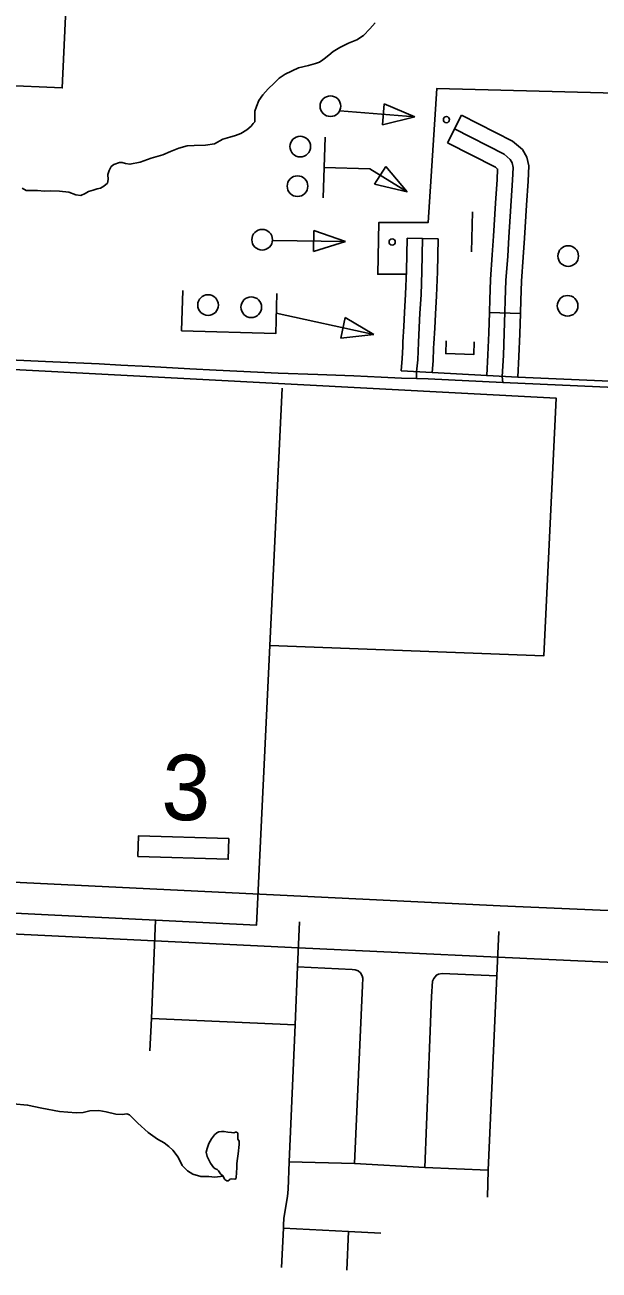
# Model space of a CAD drawing. Extents: x 653372 to 905732, y 627442 to 787275.
# Drawn here: x 684356 to 687136, y 777979 to 784006 of the extents above; entities that cross this region are included whole.
import ezdxf

# ---------------------------------------------------------------- set-up
doc = ezdxf.new("R2010")
doc.units = 0
for name, color, linetype in [('10', 7, 'Continuous'), ('33', 7, 'Continuous'), ('34', 7, 'Continuous'), ('35', 7, 'Continuous'), ('45', 7, 'Continuous'), ('5', 7, 'Continuous'), ('56', 7, 'Continuous'), ('6', 7, 'Continuous')]:
    doc.layers.add(name, color=color, linetype=linetype)

msp = doc.modelspace()

# ---------------------------------------------------------------- linework, layer by layer
at = {"layer": '10'}
for points in [[(684164.8, 779862.7), (684995.2, 779822.6), (685691.9, 779789.5), (686657, 779743.1), (687327.8, 779712.9), (687878.5, 779685.6)], [(687868.9, 779435.8), (687316, 779463.2), (686645.4, 779493.4), (685680, 779539.7), (684983.2, 779572.9), (684153, 779613)]]:
    msp.add_lwpolyline(points, dxfattribs=at)
at = {"layer": '33'}
for points in [[(684989, 779673.1), (684969.8, 779197.5), (684961.5, 779041)], [(685686, 779664.6), (685675.2, 779446.4), (685664, 779166), (685635.9, 778503), (685630.2, 778370.3), (685628.3, 778335.7), (685609.9, 778230.4), (685608.1, 778197.5), (685607.6, 778181.9), (685598.7, 777992.3)], [(686651.2, 779618.3), (686641.1, 779403.1), (686599.6, 778462.2), (686595.7, 778332)], [(685951.2, 778494.4), (685990.7, 779356.5), (685991.7, 779392), (685988.7, 779404), (685981.5, 779417.7), (685969.1, 779427.4), (685955.7, 779432.1), (685940.5, 779434.2), (685675.2, 779446.4)], [(686292, 778475.7), (686317.3, 779094.8), (686325.4, 779303.7), (686329.5, 779377.3), (686335.6, 779391.3), (686348.4, 779407), (686358, 779412.4), (686377, 779414.6), (686641.1, 779403.1)], [(684969.8, 779197.5), (685664, 779166)], [(686599.6, 778462.2), (686292, 778475.7), (685951.2, 778494.4), (685635.9, 778503)], [(685607.6, 778181.9), (685922.7, 778165.7), (686079.9, 778158.5)], [(685915, 777979.2), (685922.7, 778165.7)]]:
    msp.add_lwpolyline(points, dxfattribs=at)
at = {"layer": '34'}
for points in [[(687212.2, 782250.7), (686669.3, 782274.8), (686307.8, 782293.3), (686251.8, 782294.9), (686180.2, 782297.1), (686080.3, 782302), (685948.3, 782307.8), (685774.6, 782314.9), (685581.6, 782321.4), (685281.6, 782336), (685155.1, 782342.3), (684957.8, 782352.7), (684820.9, 782359.3), (684716, 782365.6), (684490.8, 782374.9), (684244, 782387.3), (683822.2, 782407.5), (683520.4, 782423.2), (683285.4, 782434), (682978.4, 782447.7)], [(686251.8, 782294.9), (686252.4, 782327.4)], [(686667, 782304.3), (686669.3, 782274.8)]]:
    msp.add_lwpolyline(points, dxfattribs=at)
at = {"layer": '35'}
for points in [[(686052, 784016), (686026.8, 783987.1), (685996.2, 783955.7), (685962.6, 783933.7), (685923.5, 783917.5), (685880.1, 783897.7), (685848.9, 783877.7), (685827.9, 783860.6), (685805.6, 783842.1), (685799.2, 783836.8), (685782.4, 783826.1), (685763.7, 783818.8), (685728.5, 783809.2), (685680.1, 783798.2), (685616.6, 783767.8), (685587.6, 783748.2), (685562.5, 783724.6), (685534.1, 783697.7), (685508.8, 783667.5), (685489.5, 783641.1), (685476.8, 783611.8), (685469.5, 783588.3), (685468.6, 783560.6), (685468.9, 783546.1), (685468.6, 783537.5), (685461.8, 783529.2), (685450.9, 783517), (685430.5, 783498.5), (685401.7, 783481.5), (685375.7, 783471.2), (685348.4, 783463.4), (685313.8, 783452.6)], [(685313.8, 783452.6), (685273.6, 783431), (685230.4, 783424), (685175.2, 783423.4), (685141.2, 783421.4), (685100.8, 783409.8), (685060.4, 783394.4), (685023.6, 783378.1), (684968, 783360.9), (684913.8, 783341.4), (684864.5, 783332.3), (684842.7, 783336), (684827.7, 783341), (684814.1, 783339.9), (684787.4, 783330.9), (684774.3, 783320.7), (684763.9, 783302.1), (684757.3, 783282.7), (684758.8, 783257.7), (684755.3, 783240.4), (684738.2, 783225.1), (684722.1, 783215.8), (684705.4, 783213.2), (684687.1, 783207), (684663.4, 783199.4), (684647.3, 783190.8), (684627.2, 783180.8), (684603.1, 783184.6), (684569.5, 783196.2), (684523.6, 783201.3), (684478.4, 783202.7), (684450.4, 783201.3), (684417.3, 783205.3), (684382.5, 783204.1), (684362.9, 783205.4), (684342.9, 783216.6)], [(685315.8, 778434.1), (685274.9, 778429), (685246.5, 778431.6), (685226.7, 778432.2), (685207.7, 778432.7), (685169.2, 778444.3), (685143.8, 778459.7), (685117, 778485.5), (685098.3, 778525.8), (685072.6, 778559.4), (685052.4, 778578.1), (685030.5, 778595.2), (684997.4, 778613.4), (684953.5, 778645.8), (684903.1, 778690.5), (684862, 778730.6), (684849.2, 778735.3), (684826.6, 778731.7), (684795.6, 778734.3), (684750.2, 778745.2), (684714.2, 778751.4), (684671, 778750.1), (684638.8, 778742.5), (684605.1, 778740), (684523.8, 778746.8), (684437.9, 778763.2), (684369.4, 778778.2), (684298.8, 778784.6)], [(685270.7, 778474.5), (685254.1, 778497.4), (685238.8, 778529.1), (685234.4, 778549.4), (685238.9, 778567.6), (685247.4, 778592.5), (685259.8, 778613.9), (685273.8, 778633.6), (685284.7, 778643.3), (685295.5, 778649.2), (685307.8, 778649.9), (685320.1, 778649.5)], [(685320.1, 778649.5), (685339, 778646.7), (685355.6, 778644.6), (685367.3, 778643.1), (685375.3, 778647.3), (685380.3, 778647.2), (685385.8, 778644.2), (685386.8, 778639.7), (685387.3, 778632.4), (685387.3, 778612.3), (685392.9, 778603.8), (685393.9, 778598.2), (685394.1, 778587), (685388.8, 778541.4), (685385.9, 778518.6), (685383, 778495.7), (685383, 778477.3), (685381, 778447.8), (685379.3, 778428.3), (685377.4, 778421.6), (685372.9, 778419.5), (685354.5, 778420.6), (685348.9, 778418.6), (685344.8, 778414.2), (685339.7, 778411.6), (685333.5, 778410.7), (685324.3, 778417.6), (685318.9, 778425.6), (685315.8, 778434.1), (685303.3, 778445.6), (685293.7, 778459.9), (685286.6, 778466.2), (685278.9, 778469.8), (685270.7, 778474.5)]]:
    msp.add_lwpolyline(points, dxfattribs=at)
at = {"layer": '45'}
for p, q in [((686402.1, 783435.9), (686470.3, 783569.5)), ((686206.8, 782974.1), (686356.8, 782970.8)), ((686605, 782613.9), (686754.9, 782609.4))]:
    msp.add_line(p, q, dxfattribs=at)
for points in [[(686470.3, 783569.5), (686717.4, 783443.4), (686765.1, 783403.5), (686785.8, 783365.7), (686795.4, 783323.7), (686792.1, 783250.7), (686784.6, 783134)], [(686436.2, 783502.7), (686675.7, 783380.5), (686706.1, 783355.1), (686715, 783338.8), (686720, 783316.9), (686717.2, 783254.8), (686699.5, 782979), (686693.9, 782887.6), (686684.7, 782770), (686681.9, 782673.9), (686680.1, 782615.5), (686677, 782513.7), (686672.8, 782405.4), (686667, 782304.3)], [(686402.1, 783435.9), (686634.1, 783317.5), (686644.6, 783308.7), (686642.3, 783258.8), (686634.9, 783143.6)], [(686634.9, 783143.6), (686624.6, 782983.6), (686619.1, 782892.9), (686609.8, 782774.1), (686606.9, 782676.2), (686605.1, 782617.8), (686605, 782613.9)], [(686784.6, 783134), (686774.4, 782974.3), (686768.7, 782882.4), (686759.6, 782766), (686756.8, 782671.7), (686755.1, 782613.3), (686754.9, 782609.4)], [(686206.8, 782974.1), (686203.3, 782815.3), (686199.4, 782703.1), (686193.6, 782614.6), (686190.3, 782546.4), (686186.1, 782471.9), (686185.2, 782447.8)], [(686281.8, 782972.4), (686278.3, 782813.1), (686274.3, 782699.3), (686268.4, 782610.4), (686265.2, 782542.5), (686261, 782468.4), (686257.9, 782386), (686252.4, 782327.4)], [(686356.8, 782970.8), (686353.3, 782811), (686349.2, 782695.6), (686343.3, 782606.1), (686340.1, 782538.6), (686336, 782464.9), (686335.1, 782442.1)], [(686605, 782613.9), (686602.1, 782516.3), (686597.9, 782409), (686592.1, 782308.6), (686741.9, 782301.1)], [(686754.9, 782609.4), (686752, 782511.2), (686747.8, 782401.8), (686741.9, 782301.1)], [(686185.2, 782447.8), (686183.1, 782391), (686177.5, 782331.6)], [(686335.1, 782442.1), (686332.8, 782381.1), (686327.3, 782323.3), (686177.5, 782331.6)]]:
    msp.add_lwpolyline(points, dxfattribs=at)
at = {"layer": '5'}
msp.add_lwpolyline([(685601.8, 782247.4), (685542.5, 781002.5)], dxfattribs=at)
at = {"layer": '56'}
for p, q in [((686086.9, 783523.3), (686094.9, 783625)), ((686094.9, 783625), (686243.4, 783562.1)), ((686243.4, 783562.1), (686086.9, 783523.3)), ((686049.2, 783235), (686102.9, 783321.7)), ((686102.9, 783321.7), (686206.1, 783197.8)), ((686206.1, 783197.8), (686049.2, 783235)), ((685753.8, 782909.3), (685755.4, 783011.3)), ((685755.4, 783011.3), (685907.6, 782957.9)), ((685907.6, 782957.9), (685753.8, 782909.3)), ((685885.4, 782490.6), (685907, 782590.2)), ((685907, 782590.2), (686045.7, 782507.8)), ((686045.7, 782507.8), (685885.4, 782490.6))]:
    msp.add_line(p, q, dxfattribs=at)
for points in [[(685881.4, 783590.7), (686243.4, 783562.1)], [(685809.5, 783462.4), (685800.7, 783169.3)], [(685805.1, 783315.8), (686026.2, 783309.2), (686206.1, 783197.8)], [(686523.9, 783102.2), (686518.1, 782907.7)], [(685556, 782963.5), (685907.6, 782957.9)], [(685120.7, 782720.3), (685114.8, 782525.8), (685570.4, 782512.1), (685576.2, 782706.6)], [(685573.4, 782610.7), (686045.7, 782507.8)], [(686395.8, 782476.6), (686394, 782415.3), (686529.8, 782411.3), (686531.7, 782472.5)]]:
    msp.add_lwpolyline(points, dxfattribs=at)
msp.add_lwpolyline([(684903, 779981.2), (684906, 780081.2), (685343.4, 780068.1), (685340.3, 779968.1)], close=True, dxfattribs=at)
for centre, radius in [((685835.4, 783612.9), 50), ((686397.1, 783548.1), 15), ((685689.2, 783417.5), 50), ((685675.9, 783225.8), 50), ((685504.9, 782966.6), 50), ((686134.3, 782955.9), 15), ((686986.4, 782887.5), 50), ((685242.8, 782650.4), 50), ((685452, 782639.9), 50), ((686983.5, 782646.7), 50)]:
    msp.add_circle(centre, radius, dxfattribs=at)
at = {"layer": '6'}
for points in [[(680427.7, 783895.4), (680402.5, 783400.9), (682535.7, 783293.6), (682658.4, 783288.4), (683017.2, 783280.2), (683042.3, 783766.1), (684536.7, 783701.7), (684597.3, 785016.9), (684391.3, 785026.4), (684425.2, 785508.2), (684469.9, 786348.1), (685789.1, 786281.8), (686863.5, 786226.6)], [(688293.1, 783293.2), (687264.3, 783349.2), (687280.7, 783675), (686351.1, 783698.8), (686308.7, 783050.5), (686070.2, 783050.3), (686064.2, 782799.5), (686202.8, 782799.6)], [(686741.9, 782301.1), (687187.8, 782282.3), (687222.2, 782906.5), (687793.9, 782885.6), (688275.1, 782861.5)], [(682938.8, 779774.7), (685478.1, 779648.9), (685542.5, 781002.5), (686869.1, 780952.6), (686927.5, 782199.7), (682985.6, 782407.8), (682965.5, 782161.4), (682951.2, 781822.7)], [(686327.3, 782323.3), (686592.1, 782308.6)]]:
    msp.add_lwpolyline(points, dxfattribs=at)

# ---------------------------------------------------------------- texts
at = {"layer": '56'}
msp.add_text('3', height=316.8, rotation=358.28003, dxfattribs=at).set_placement((685014.6, 780160.4))

doc.saveas('drawing.dxf')
